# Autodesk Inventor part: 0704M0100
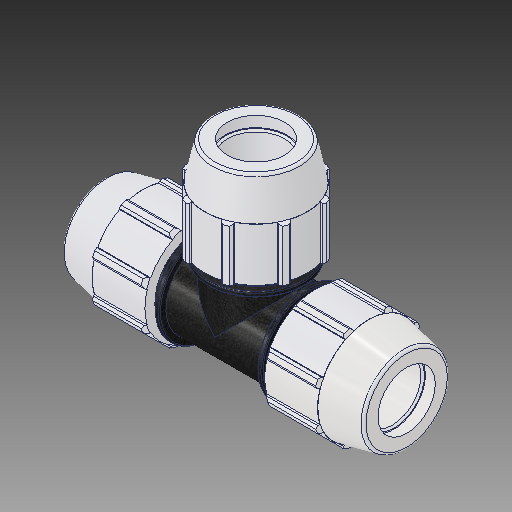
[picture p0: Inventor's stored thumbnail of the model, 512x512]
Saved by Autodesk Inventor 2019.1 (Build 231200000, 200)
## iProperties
Created: 2017-02
Part Number: 0704M0100
Material: PVC-Piping
Description: PLASSON TEE 1'' - 1'' - 1''
Document SubType Name: Modeling
Designer: KIM
Mass: 92.6774 g
Surface Area: 199.44 cm^2
Volume: 66.1981 cm^3
Density: 1.4 g/cm^3
Appearance: PTFE
Author: KIM
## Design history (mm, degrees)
derived "0704M0.ipt"
feature "Solid1::0704M0.ipt"
tag "TaggingFeature1"
body "Solid1"
other parameters: "d2" = 33.3, "d4" = 7.32367, "d5" = 21.971, "d7" = 64.008, "d11" = 2.92947, "d13" = 120 deg, "d14" = 49.95, "d15" = 12 deg, "d16" = 55.68696, "d18" = 1.665, "d19" = 35 deg, "d20" = 17.5 deg, "d21" = 59.52744, "d23" = 0, "d25" = 360 deg, "d27" = 1.28016, "d33" = 0.666, "d42" = 30.7594, "d43" = 1.92024, "d46" = 0.999, "d63" = 65.024, "d67" = 48.006, "d76" = 33.3, "d77" = 64.008, "d78" = 12 deg, "d79" = 87.884, "d80" = 120 deg, "d81" = 49.95, "d82" = 7.32367, "d85" = 48.006, "d86" = 55.68696, "d87" = 2.92947, "d88" = 2.92947, "d89" = 21.971, "d90" = 30.7594, "d96" = 5.85893, "d98" = 59.52744, "d99" = 35 deg, "d100" = 17.5 deg, "d102" = 0, "d103" = 1.28016, "d107" = 360 deg, "d109" = 0.999, "d112" = 1.665, "d118" = 360 deg, "d121" = 0, "d128" = 175.006, "d131" = 29.97, "d132" = 29.97, "d133" = 65.024, "d134" = 1.30048, "d135" = 5.85893, "d152" = 0, "d154" = 0, "d156" = 0, "d158" = 0, "d_" = 33.3, "E_" = 64.008, "A_" = 87.884, "l_" = 65.024, "H_" = 175.006
